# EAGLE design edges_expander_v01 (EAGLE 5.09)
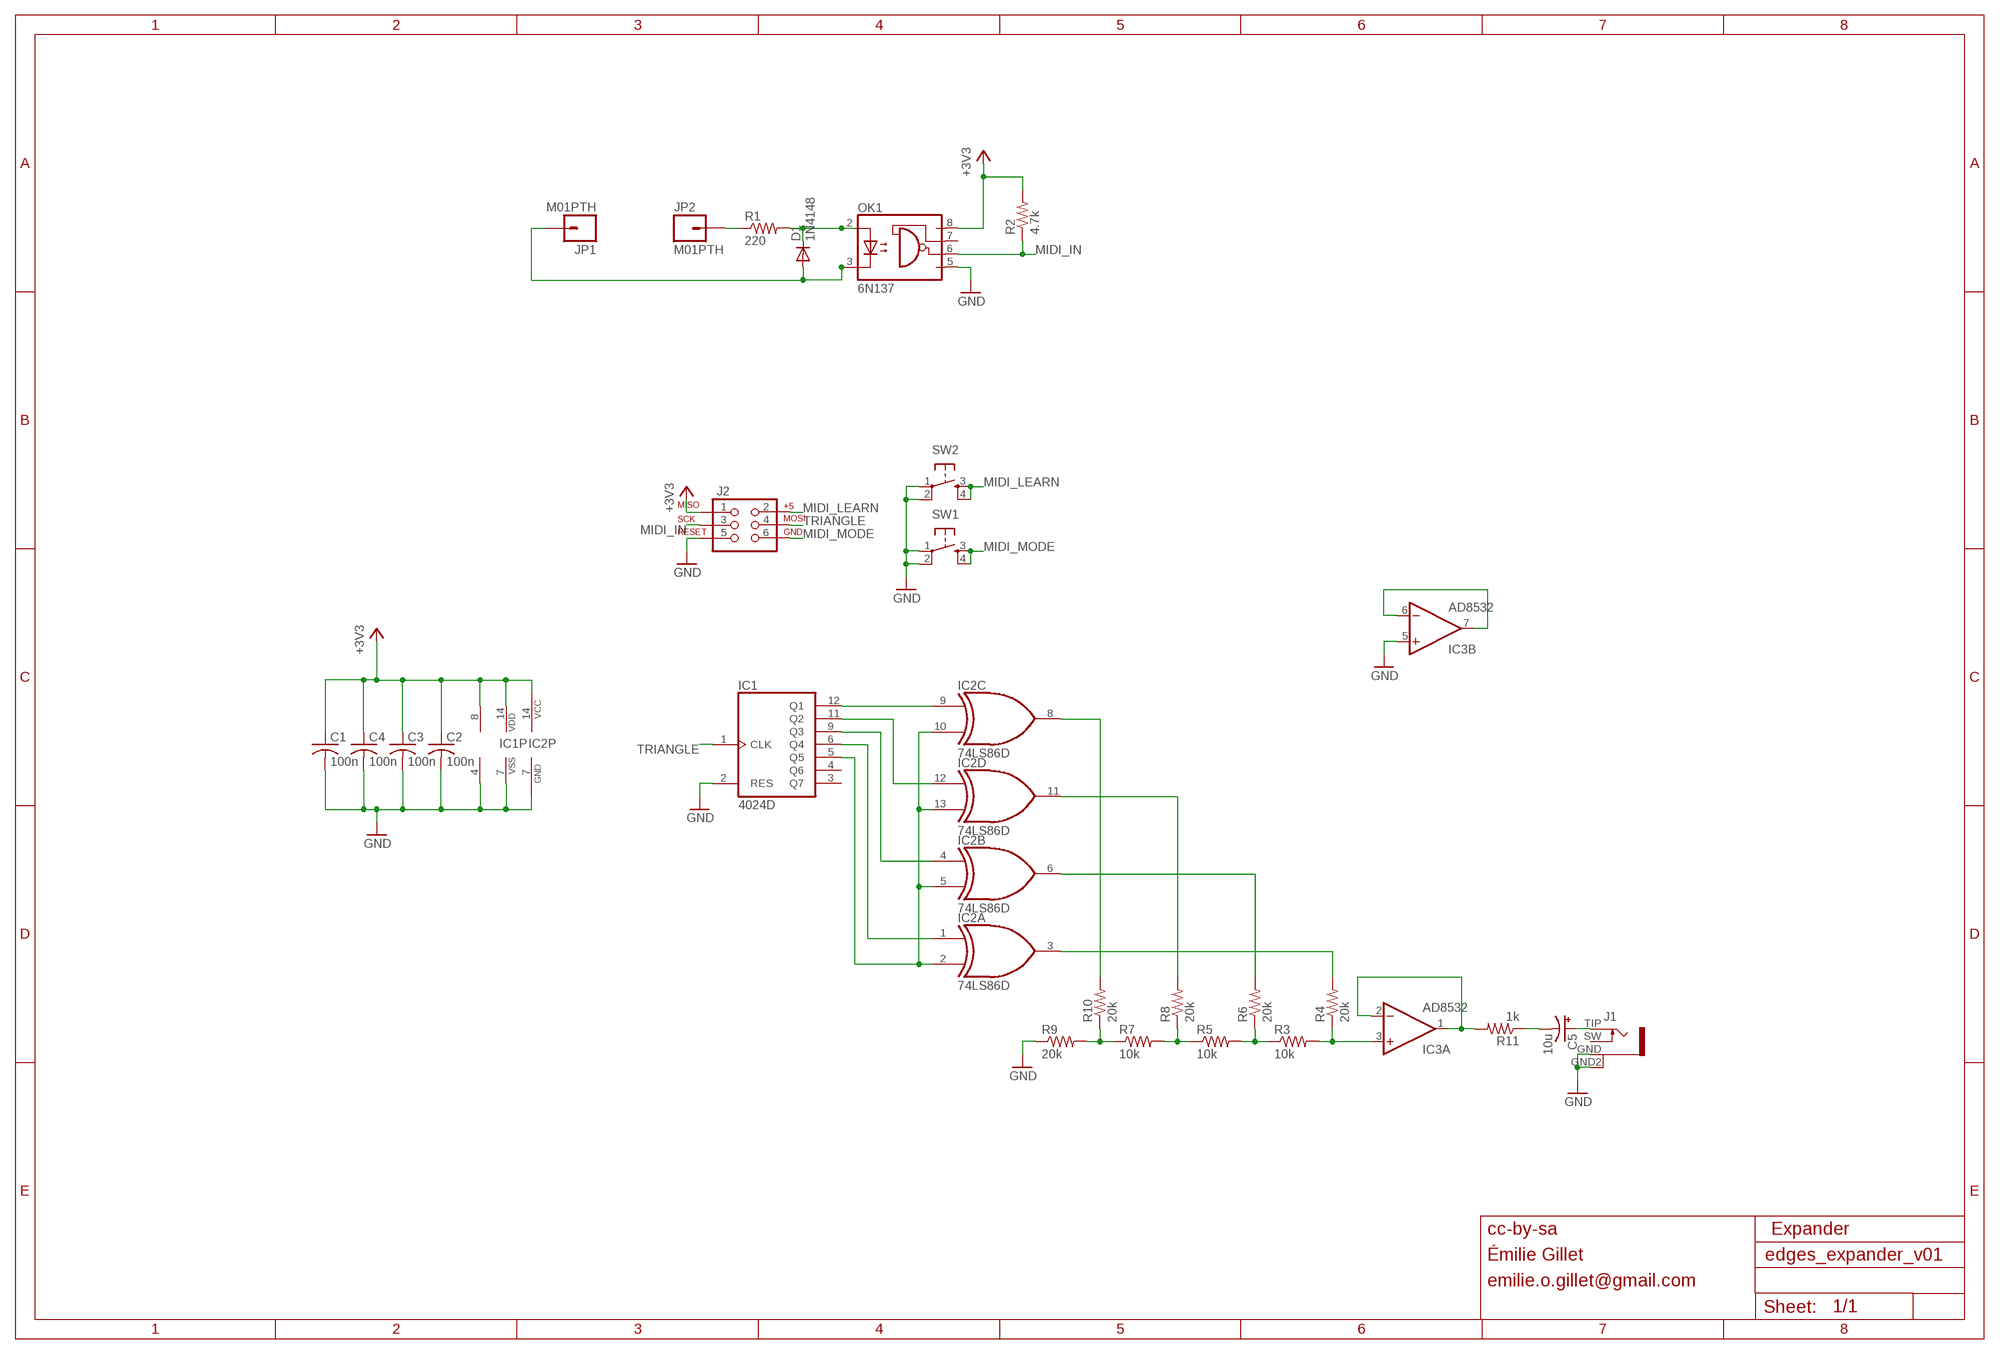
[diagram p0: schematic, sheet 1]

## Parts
C1  100n  C-USC0603  [C0603]
C2  100n  C-USC0603  [C0603]
C3  100n  C-USC0603  [C0603]
C4  100n  C-USC0603  [C0603]
C5  10u  CPOL-USB  [PANASONIC_B]
D1  1N4148  DIODE-SOD323-W  [SOD323-W]
IC1  4024D  [SO14]
IC2  74LS86D  [SO14]
IC3  AD8532  TL072D  [SO08]
J1  PJ301WQP  [WQP_PJ_301BM]
J2  AVR_SPI_PRG_6PTH  [2X3]
JP1  M01PTH  [1X01]
JP2  M01PTH  [1X01]
OK1  6N137  6N137SMT  [DIL8-SMD]
R1  220  R-US_R0603  [R0603]
R2  4.7k  R-US_R0603  [R0603]
R3  10k  R-US_R0603  [R0603]
R4  20k  R-US_R0603  [R0603]
R5  10k  R-US_R0603  [R0603]
R6  20k  R-US_R0603  [R0603]
R7  10k  R-US_R0603  [R0603]
R8  20k  R-US_R0603  [R0603]
R9  20k  R-US_R0603  [R0603]
R10  20k  R-US_R0603  [R0603]
R11  1k  R-US_R0603  [R0603]
SW1  TAC_SWITCHPTH  [TACTILE-PTH]
SW2  TAC_SWITCHPTH  [TACTILE-PTH]

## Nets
+3V3_EXP: C1.1 C2.1 C3.1 C4.1 IC1.14(VDD) IC2.14(P:VCC) IC3.8(P:V+) J2.1 OK1.8(VCC) R2.2 ; supply symbol labelled +3V3
GND: C1.2 C2.2 C3.2 C4.2 IC1.2(RES) IC1.7(VSS) IC2.7(P:GND) IC3.4(P:V-) IC3.5(B:+IN) J1.GND J1.GND2 J2.5 OK1.5(GND) R9.1 SW1.1 SW1.2 SW2.1 SW2.2
MIDI_IN: J2.3 OK1.6(VO) R2.1
MIDI_IN4: JP2.1 R1.1
MIDI_IN5: D1.A JP1.1 OK1.3(C)
MIDI_LEARN: J2.2 SW2.3 SW2.4
MIDI_MODE: J2.6 SW1.3 SW1.4
N$1: IC2.3(A:O) R4.2
N$2: IC2.6(B:O) R6.2
N$3: IC2.11(D:O) R8.2
N$4: IC2.8(C:O) R10.2
N$38: D1.C OK1.2(A) R1.2
N$49: IC1.5(Q5) IC2.2(A:I1) IC2.5(B:I1) IC2.10(C:I1) IC2.13(D:I1)
N$50: IC1.9(Q3) IC2.4(B:I0)
N$51: IC1.11(Q2) IC2.12(D:I0)
N$52: IC1.12(Q1) IC2.9(C:I0)
N$54: IC3.6(B:-IN) IC3.7(B:OUT)
N$56: IC1.6(Q4) IC2.1(A:I0)
N$58: R7.1 R9.2 R10.1
N$59: R5.1 R7.2 R8.1
N$60: R3.1 R5.2 R6.1
N$61: IC3.3(A:+IN) R3.2 R4.1
N$64: C5.- R11.1
N$65: IC3.1(A:OUT) IC3.2(A:-IN) R11.2
N$66: C5.+ J1.TIP
TRIANGLE: IC1.1(CLK) J2.4
Unconnected: IC1.3(Q7) IC1.4(Q6) J1.SW OK1.7(VE)

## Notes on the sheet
- cc-by-sa | Expander
- Émilie Gillet
- emilie.o.gillet@gmail.com

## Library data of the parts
C1-C4 = rcl:C-US: CAPACITOR, American symbol
C5 = rcl:CPOL-US: POLARIZED CAPACITOR, American symbol
D1 = diode:DIODE-: DIODE
IC1 = 40xx:4024: 7-stage binary/ripple COUNTER
IC2 = 74xx-us:74*86: Quad 2-input EXCLUSIV-OR (XOR) gate
IC3 = og-linear:TL072: OP AMP
J1 = og-pj301:PJ301
J2 = SparkFun:AVR_SPI_PRG_6: AVR ISP 6 Pin This is the reduced ISP connector for AVR programming. Common on Arduino. This footprint will take up less PCB space and can be used with a 10-pin to 6-pin adapter such as SKU: BOB-08508
JP1 JP2 = SparkFun:M01: Header 1
OK1 = og-optocouplers:6N137: MOTOROLA OPTO COUPLER
R1-R11 = rcl:R-US_: RESISTOR, American symbol
SW1 SW2 = SparkFun:TAC_SWITCH: Momentary Switch Button commonly used for reset or general input. Spark Fun Electronics SKU : COM-00097

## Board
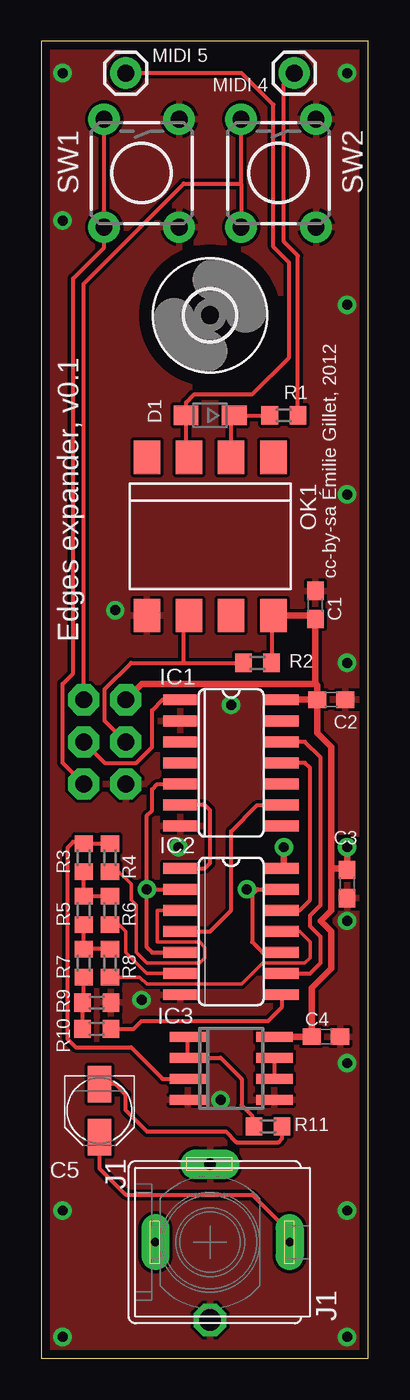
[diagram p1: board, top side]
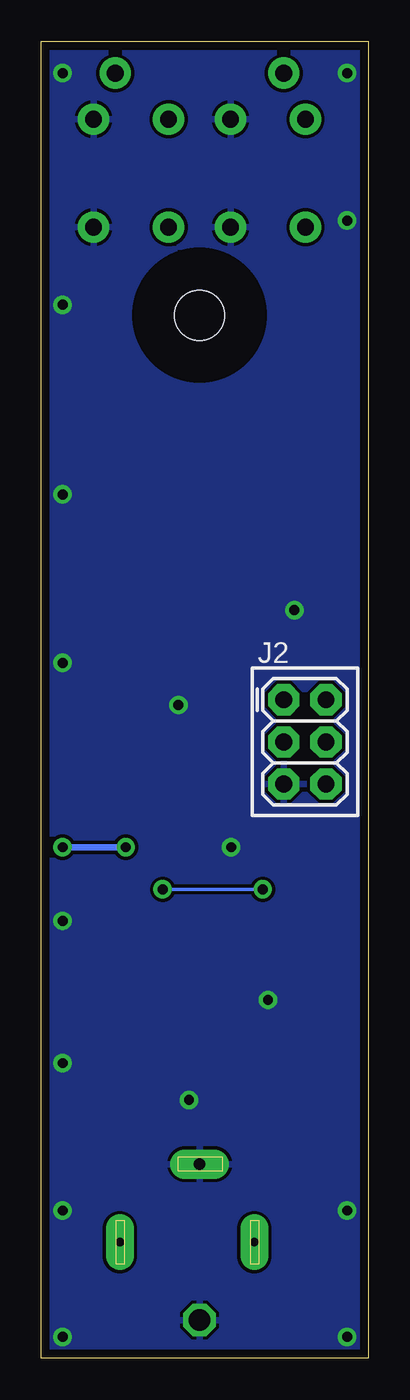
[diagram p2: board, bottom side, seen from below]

Size 19.68 x 79.38 mm. Coordinates in mm from the lower left corner, seen from the top.
Outline: 19.68,79.38 0,79.38 0,0 19.68,0 19.68,79.38
Copper layers (1*16): Top 0.035mm / dielectric 1.5mm / Bottom 0.035mm
Design rules "PCBCart-Standard *": minimum track width 8mil, minimum drill 0.4mm, track to track 8mil, track to pad 8mil, pad to pad 8mil, via to via 8mil, smd to smd 8mil, copper to edge 20mil, drill to drill 8mil, minimum pad ring 8mil, minimum via ring 10mil, stop-mask expansion 3mil, vias tented up to drill 0mil, thermal gap 8mil

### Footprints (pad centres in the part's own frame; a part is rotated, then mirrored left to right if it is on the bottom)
C0603 = smd 1.1 x 1: 1 -0.85,0; 2 0.85,0
PANASONIC_B = smd 2.2 x 1.4: + 1.6,0; - -1.6,0
SOD323-W = smd 1.5 x 1.2: A 1.45,0; C -1.45,0
SO14 = smd 0.66 x 2.032: 1 -3.81,-3.073; 2 -2.54,-3.073; 3 -1.27,-3.073; 4 0,-3.073; 5 1.27,-3.073; 6 2.54,-3.073; 7 3.81,-3.073; 8 3.81,3.073; 9 2.54,3.073; 10 1.27,3.073; 11 0,3.073; 12 -1.27,3.073; 13 -2.54,3.073; 14 -3.81,3.073
SO08 = smd 0.6 x 2.2: 1 -1.905,-2.6; 2 -0.635,-2.6; 3 0.635,-2.6; 4 1.905,-2.6; 5 1.905,2.6; 6 0.635,2.6; 7 -0.635,2.6; 8 -1.905,2.6
WQP_PJ_301BM = drill 0.7 pad 1.778 long: GND -4.7,0 | drill 1.3 octagon: GND2 4.7,0 | drill 0.5 pad 1.676 long: SW 0,-3.3; TIP 0,4.8
2X3 = drill 1.016 pad 1.88 octagon: 1 0,0; 2 0,2.54; 3 2.54,0; 4 2.54,2.54; 5 5.08,0; 6 5.08,2.54
1X01 = drill 1.016 pad 1.88 round: 1 0,0
DIL8-SMD = smd 1.6 x 2: 1 -3.81,-4.77; 2 -1.27,-4.77; 3 1.27,-4.77; 4 3.81,-4.77; 5 3.81,4.77; 6 1.27,4.77; 7 -1.27,4.77; 8 -3.81,4.77
R0603 = smd 1 x 1.1: 1 -0.85,0; 2 0.85,0
TACTILE-PTH = drill 1.016 pad 1.88 round: 1 -3.251,2.261; 2 3.251,2.261; 3 -3.251,-2.261; 4 3.251,-2.261
3,0 = hole 3: 0,0

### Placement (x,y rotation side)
C1  16.51,45.4 90 top
C2  17.46,39.69 0 top
C3  18.41,28.57 270 top
C4  17.14,19.37 0 top
C5  3.49,14.92 270 top
D1  10.16,56.83 180 top
IC1  11.43,35.88 270 top
IC2  11.43,25.72 270 top
IC3  11.43,17.46 270 top
J1  10.16,6.99 270 top
J2  5.08,39.69 270 bottom
JP1  5.08,77.47 0 top
JP2  15.24,77.47 0 top
OK1  10.16,49.53 180 top
R1  14.61,56.83 180 top
R2  13.02,41.91 0 top
R3  2.54,30.16 90 top
R4  4.13,30.16 270 top
R5  2.54,26.99 90 top
R6  4.13,26.99 270 top
R7  2.54,23.81 90 top
R8  4.13,23.81 270 top
R9  3.33,21.43 180 top
R10  3.33,19.84 0 top
R11  13.65,13.97 180 top
SW1  6.03,71.44 270 top
SW2  14.29,71.44 270 top
U$1  [3,0]  10.16,62.87 0 top

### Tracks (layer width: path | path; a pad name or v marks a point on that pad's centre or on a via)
+3V3_EXP  (via drill 0.6)
  Top 0.203: IC2.14 14.29,29.53
  Top 0.254: OK1.8 13.87,44.66 R2.2
  Top 0.406: OK1.8 16.3,44.76 C1.1 16.51,40.64 | 16.83,39.58 16.73,39.69 C2.1 | 17.46,29.53 17.46,26.99 16.83,26.35 17.46,25.72 17.46,23.5 16.3,22.33 C4.1 IC3.8 | 17.46,29.53 17.46,36.83 16.61,37.68 C2.1 | IC2.14 14.61,29.63 v14.61,30.8 | J2.1 6.03,40.64 16.51,40.64 | 16.51,40.64 16.61,40.54 C2.1 | C2.1 IC1.14 | v18.41,30.8 C3.1 18.31,29.53 17.46,29.53
  Bottom 0.406: v18.41,30.8 v14.61,30.8
GND  (via drill 0.6)
  other vias: 8.26,30.8 6.03,21.59 18.41,26.35 4.45,45.08 10.79,15.56 1.27,77.47 18.41,77.47 1.27,68.58 1.27,1.27 1.27,8.89 18.41,1.27 18.41,8.89 18.41,17.78 18.41,41.91 18.41,52.07 18.41,63.5 11.43,39.37
  pour Top (isolate 0.203): 0,79.38 0,0 19.68,0 19.68,79.38
  pour Bottom: 0,79.38 0,0 19.68,0 19.68,79.38
MIDI_IN
  Top 0.254: J2.3 3.81,38.42 3.81,40.32 5.4,41.91 8.57,41.91 | 8.57,41.91 R2.1 | OK1.6 8.57,44.44 8.57,41.91
MIDI_IN4
  Top 0.254: JP2.1 14.61,76.84 14.61,67.31 15.46,66.46 R1.1
MIDI_IN5
  Top 0.254: OK1.3 8.71,54.48 D1.A 8.71,57.6 9.21,58.1 12.7,58.1 14.92,60.32 14.92,66.04 13.97,66.99 13.97,75.56 12.06,77.47 JP1.1
MIDI_LEARN
  Top 0.254: J2.2 2.54,64.77 8.57,70.8 12.03,70.8 | 11.99,68.19 SW2.4 12.03,70.8 | 12.03,70.8 SW2.3
MIDI_MODE
  Top 0.254: SW1.3 SW1.4 3.77,66.95 1.91,65.09 1.91,41.27 1.27,40.64 1.27,35.88 J2.6
N$1
  Top 0.203: IC2.3 6.99,26.99 6.99,25.08 9.53,25.08 9.84,24.77 9.84,24.13 9.53,23.81 6.35,23.81 5.71,24.45 5.71,27.3 5.4,27.62 5.4,28.57 4.66,29.31 R4.2
N$2
  Top 0.203: IC2.6 6.35,23.18 5.08,24.45 5.08,25.72 4.66,26.14 R6.2
N$3
  Top 0.203: IC2.11 15.56,25.72 16.19,25.08 16.19,24.13 15.88,23.81 13.34,23.81 12.06,22.54 6.35,22.54 5.93,22.96 R8.2
N$4
  Top 0.254: IC2.8 14.5,21.17 13.65,20.32 6.03,20.32 5.56,19.84 R10.2
N$38
  Top 0.254: R1.2 D1.C 11.43,56.65 OK1.2
N$49  (via drill 0.6)
  Top 0.203: v12.38,28.26 12.7,27.94
  Top 0.254: IC1.5 6.99,34.61 6.67,34.29 6.67,33.02 6.35,32.7 v6.35,28.26 | v6.35,28.26 6.35,24.77 6.67,24.45 IC2.5 | v6.35,28.26 IC2.2 | IC2.13 13.02,28.26 12.7,27.94 12.7,25.08 13.34,24.45 IC2.10
  Bottom 0.203: v6.35,28.26 v12.38,28.26
N$50
  Top 0.254: IC1.9 13.02,33.34 11.43,31.75 11.43,26.99 10.16,25.72 IC2.4
N$51
  Top 0.254: IC1.11 15.88,35.88 16.19,35.56 16.19,27.62 15.56,26.99 IC2.12
N$52
  Top 0.254: IC1.12 15.88,37.15 16.83,36.2 16.83,27.3 16.19,26.67 16.19,26.04 16.83,25.4 16.83,23.81 16.19,23.18 IC2.9
N$54
  Top 0.254: IC3.7 IC3.6
N$56
  Top 0.254: IC2.1 9.84,29.53 10.16,29.84 10.16,33.02 9.84,33.34 IC1.6
N$58
  Top 0.254: R10.1 | R10.1 R9.2 2.54,21.49 R7.1
N$59
  Top 0.254: R5.1 R7.2 R8.1
N$60
  Top 0.254: R3.1 R5.2 R6.1
N$61
  Top 0.254: 8.89,16.83 IC3.3 7.3,16.83 5.4,18.73 2.06,18.73 1.59,19.21 1.59,30.8 1.91,31.11 2.44,31.11 R3.2 R4.1
N$64
  Top 0.254: C5.- 4.43,16.52 5.08,15.88 5.08,14.92 6.35,13.65 11.11,13.65 11.75,13.02 14.29,13.02 14.5,13.23 R11.1
N$65
  Top 0.254: IC3.1 IC3.2 10.79,18.1 12.06,16.83 12.06,15.24 12.7,14.61 12.7,14.07 R11.2
N$66
  Top 0.254: J1.TIP 14.61,7.34 14.61,7.94 12.7,9.84 5.08,9.84 3.49,11.43 C5.+
TRIANGLE
  Top 0.254: 8.26,39.69 IC1.1 7.3,39.69 6.67,39.05 6.67,36.83 5.71,35.88 3.81,35.88 J2.4

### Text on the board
tPlace: MIDI 5 | MIDI 4
tNames: cc-by-sa Émilie Gillet, 2012 | Edges expander, v0.1 | J1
